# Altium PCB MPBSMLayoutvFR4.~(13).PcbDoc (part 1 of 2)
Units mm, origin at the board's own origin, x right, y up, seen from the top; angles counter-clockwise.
Board outline 131.7 x 110.39 mm, 4 copper layers (Top Layer, Power, GroundPlane, Bottom Layer), stack 2.286 mm thick; 156 components, 77 nets, 429 pads, 117 vias.
Unrouted connection lines stored in the file: 25.
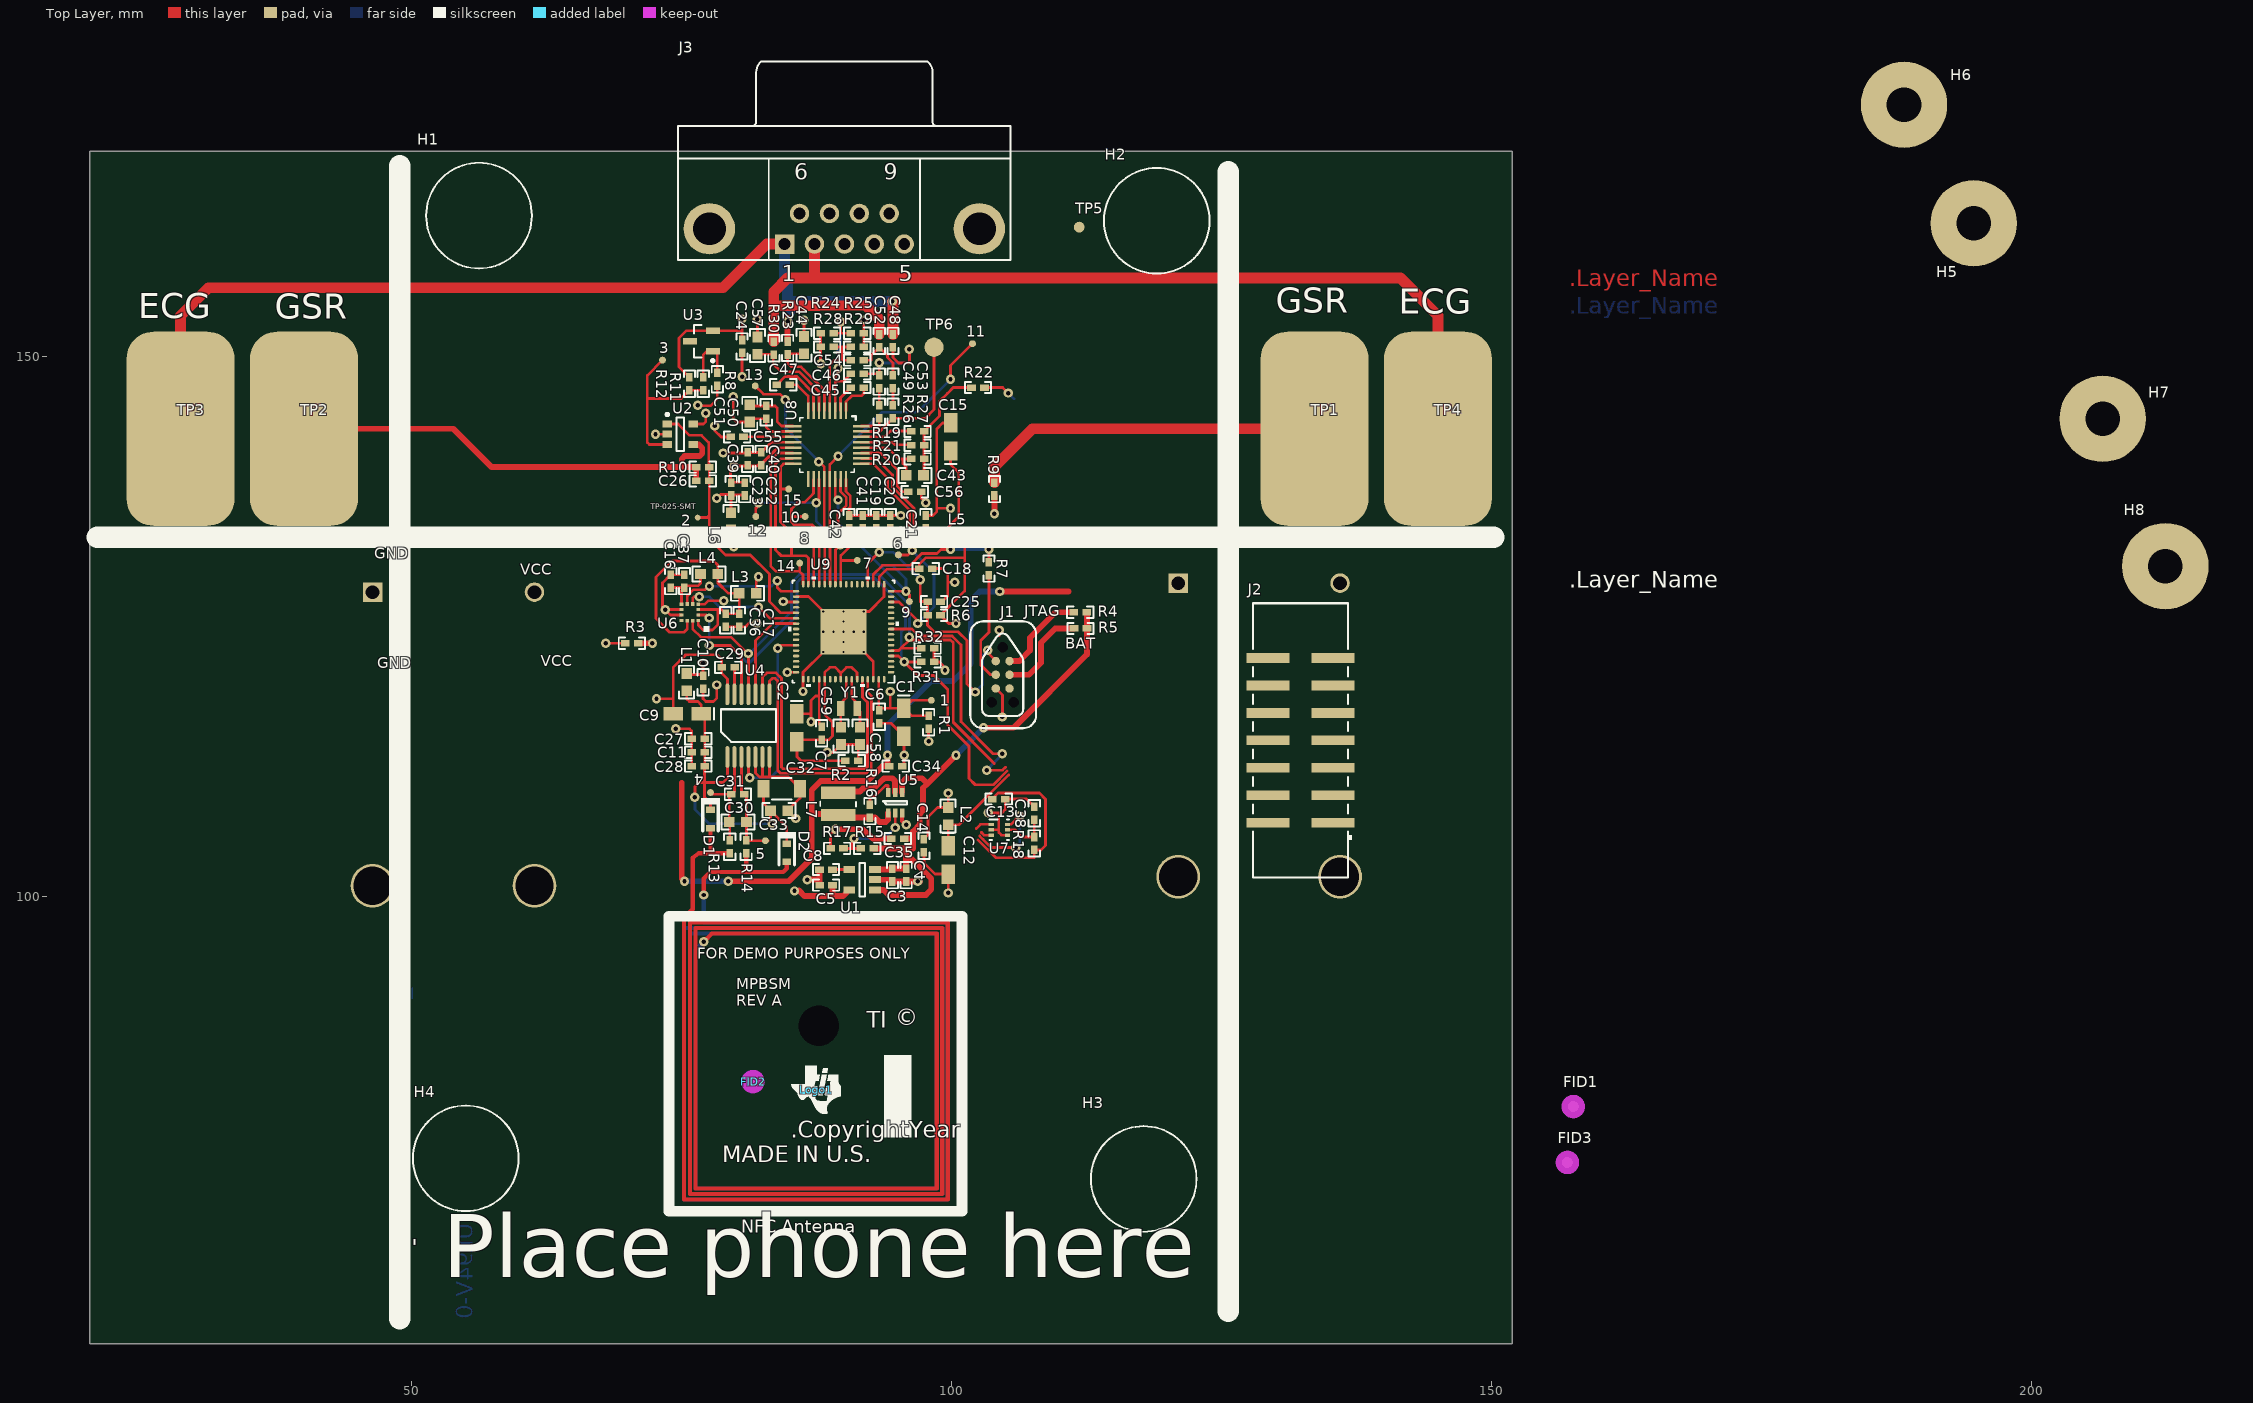
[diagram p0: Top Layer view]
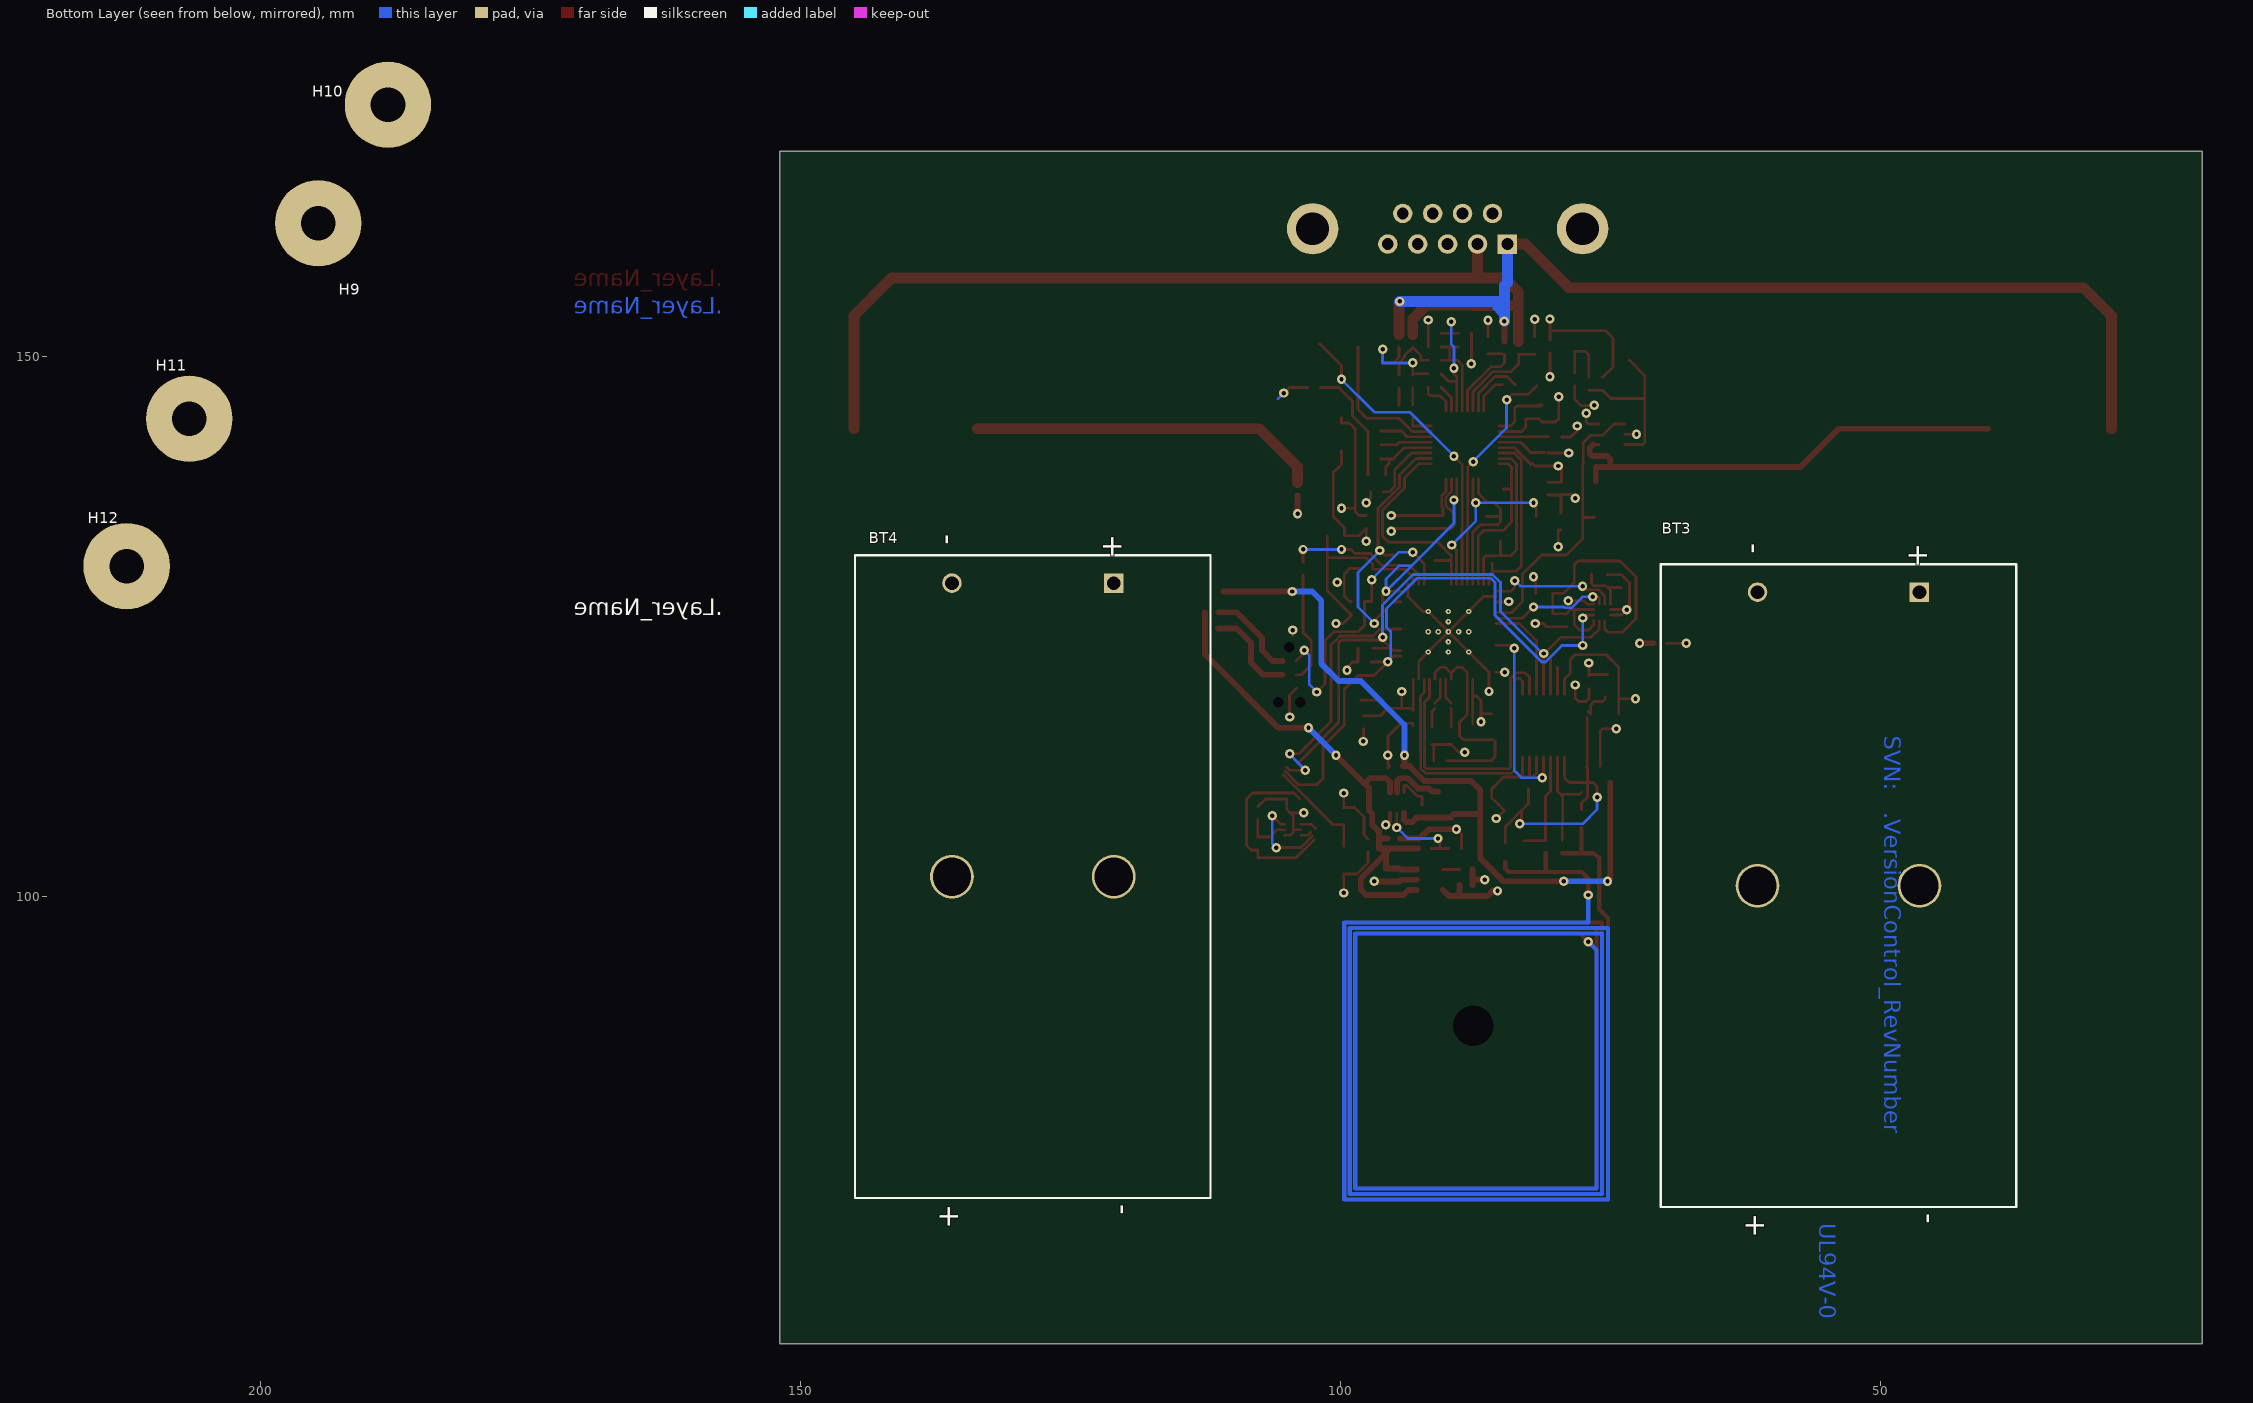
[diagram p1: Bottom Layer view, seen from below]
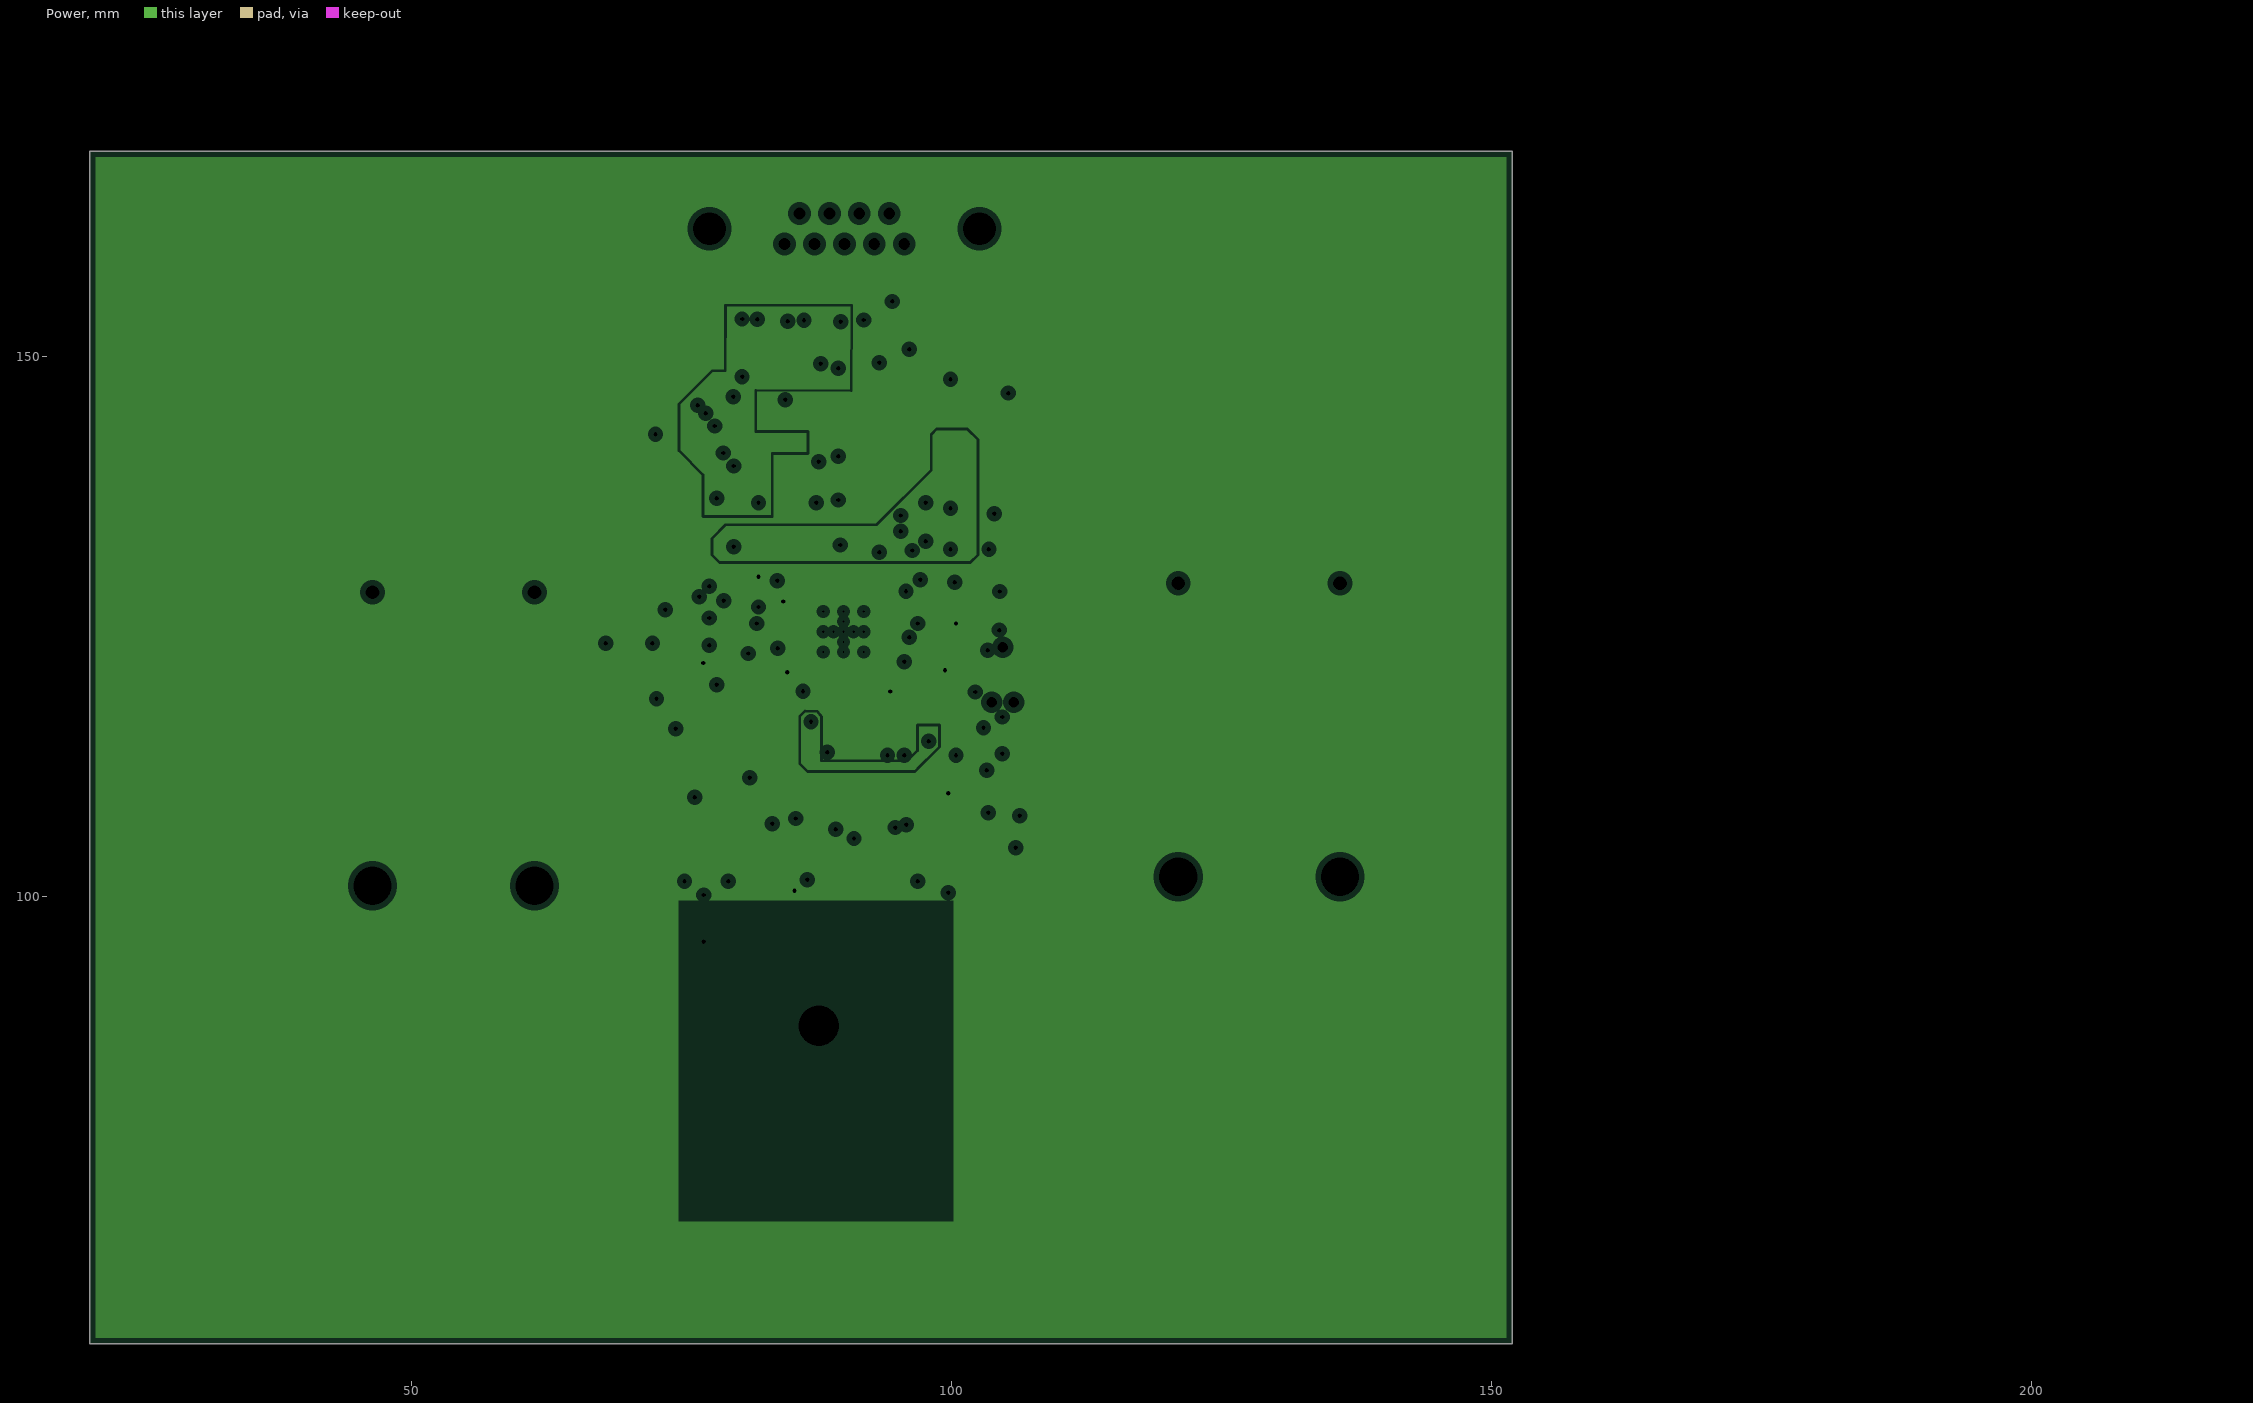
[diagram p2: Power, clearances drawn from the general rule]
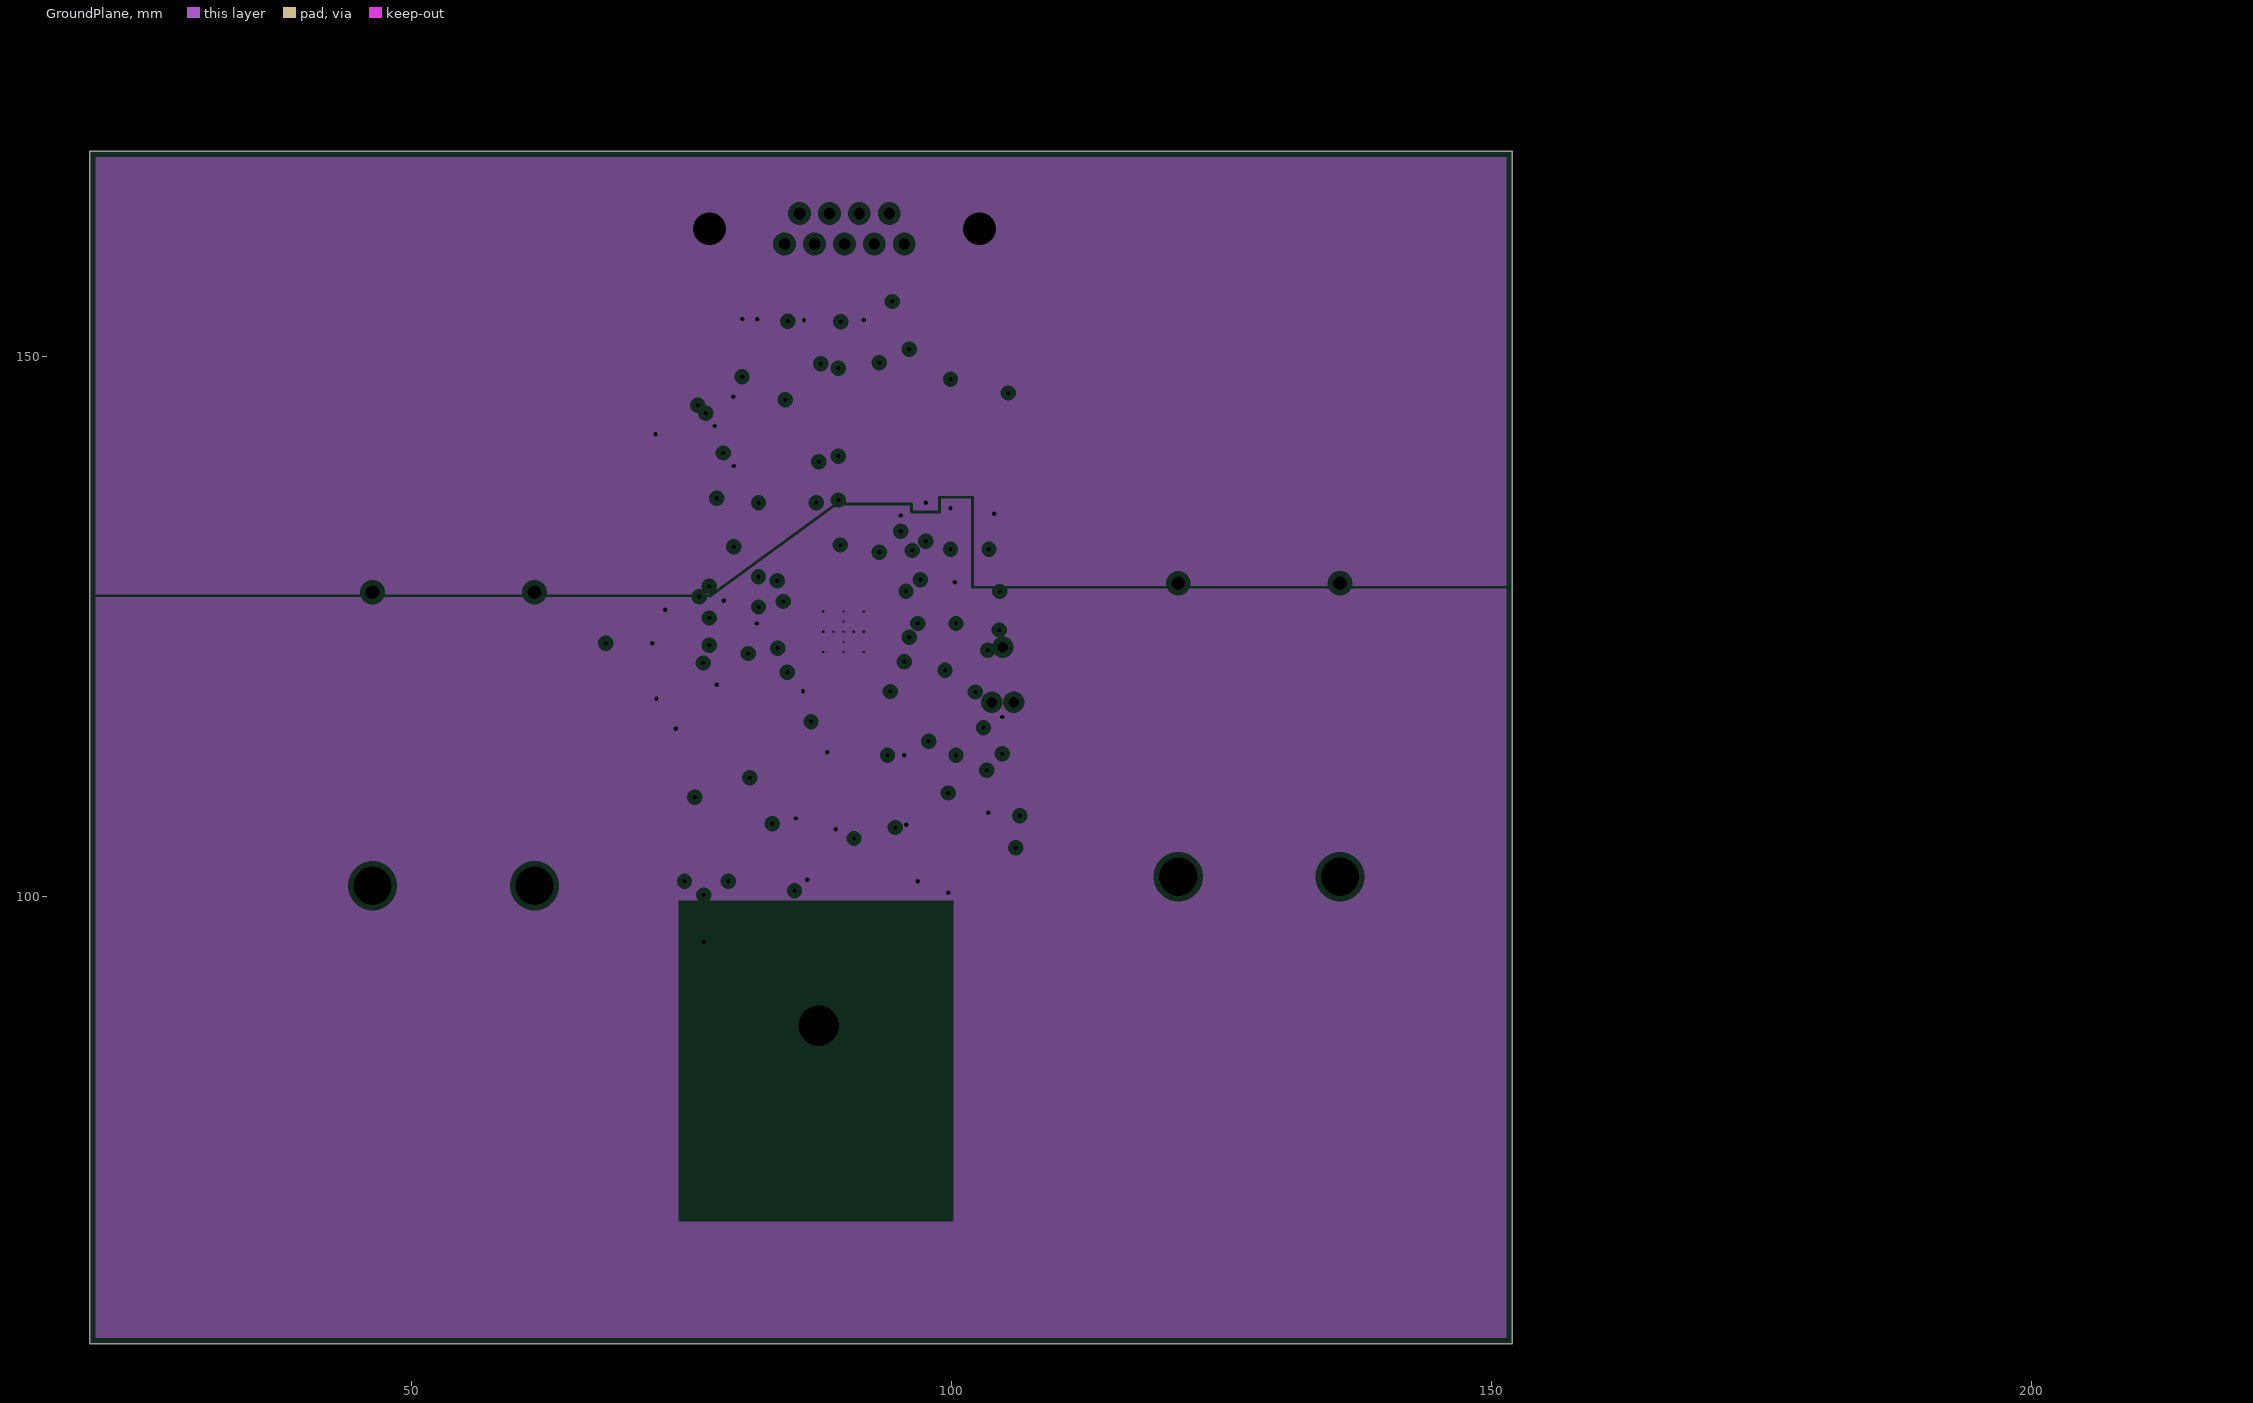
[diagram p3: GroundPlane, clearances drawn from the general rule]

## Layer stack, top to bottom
Top Solder: solder mask 0.0102, Solder Resist, Dk 3.5
Top Layer: signal copper 0.0356
Dielectric1: core 1.5037, FR-4, Dk 4.8
Power: plane copper 0.0356, net DVCC
Dielectric2: prepreg 0.32, FR-4, Dk 4.8
GroundPlane: plane copper 0.0356, net GND
Dielectric3: core 0.32, FR-4, Dk 4.8
Bottom Layer: signal copper 0.0356
Bottom Solder: solder mask 0.0102, Solder Resist, Dk 3.5

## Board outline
20.218,169.037 20.218,58.649 150.825,58.649 151.917,58.649 151.917,158.471 151.917,169.037 20.218,169.037

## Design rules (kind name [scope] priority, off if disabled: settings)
AcuteAngle [All] p1: minimum=4.50000000000000E+0001 checktracksonly=FALSE
AssemblyTestPointUsage [All] p1: valid=2
Clearance Clearance_BoardEdge_MountingHoles [OnCopper and InComponentClass('Mounting Holes') vs IsKeepOut] p1: gap=1.016
Clearance Clearance_BoardEdge_Poly [OnCopper and InPoly vs IsKeepOut] p2: gap=0.635
Clearance Clearance_BoardEdge [OnCopper and Not InComponentClass('Logo') and not InComponentClass('FiducialMark') and not InRegion(1000,500,4000,800) and Not IsKeepout vs IsKeepOut] p3: gap=1.905
Clearance Clearance_Poly [InPolygon] p4: gap=0.635
Clearance [All] p5: gap=0.1
ComponentClearance ComponentClearance_Shunt [InComponentClass('Header') vs InComponentClass('Shunt')] p1: gap=0 collisioncheckmode=3 verticalgap=0 showdistances=FALSE
ComponentClearance ComponentClearance_MountingHoles_FiducialMarks [InComponentClass('Mounting Holes') vs InComponentClass('FiducialMark')] p2: gap=1.27 collisioncheckmode=3 verticalgap=0.254 showdistances=FALSE
ComponentClearance ComponentClearance_Logo [InComponentClass('Logo')] p3: gap=1.27 collisioncheckmode=3 verticalgap=0.254 showdistances=FALSE
ComponentClearance ComponentClearance_ScrewToNut [(HasFootprint('NY PMS 440 0025 PH')) vs (HasFootprint('Keystone_1902C'))] p4: gap=0.127 collisioncheckmode=3 verticalgap=0.254 showdistances=FALSE
ComponentClearance ComponentClearance_MountingHoles [InComponentClass('Mounting Holes')] p5: gap=6.35 collisioncheckmode=3 verticalgap=2540 showdistances=FALSE
ComponentClearance ComponentClearance_SmallPassives [HasFootprint('0201*') or HasFootprint('0402*') or HasFootprint('0508') or HasFootprint('0603*') or HasFootprint('0612') or HasFootprint('0805*') or HasFootprint('0815*') or HasFootprint('0830*') or HasFootprint('1206*') or HasFootprint('1210*') or HasFootprint('1808*') or HasFootprint('1812*') or HasFootprint('1825*') or HasFootprint('2010*') or HasFootprint('2220*') or HasFootprint('2225*') or HasFootprint('2512*') or HasFootprint('2728*') or HasFootprint('3518*') vs HasFootprint('0201*') or HasFootprint('0402*') or HasFootprint('0508') or HasFootprint('0603*') or HasFootprint('0612') or HasFootprint('0805*') or HasFootprint('0815*') or HasFootprint('0830*') or HasFootprint('1206*') or HasFootprint('1210*') or HasFootprint('1808*') or HasFootprint('1812*') or HasFootprint('1825*') or HasFootprint('2010*') or HasFootprint('2220*') or HasFootprint('2225*') or HasFootprint('2512*') or HasFootprint('2728*') or HasFootprint('3518*')] p6: gap=0.508 collisioncheckmode=3 verticalgap=0.254 showdistances=FALSE
ComponentClearance ComponentClearance_THtoSMT [IsThruComponent vs IsSMTComponent] p7: gap=2.54 collisioncheckmode=3 verticalgap=0.762 showdistances=FALSE
ComponentClearance ComponentClearance_THtoTH [IsThruComponent vs IsThruComponent] p8: gap=3 collisioncheckmode=3 verticalgap=0.762 showdistances=FALSE
ComponentClearance [All] p9: gap=1.016 collisioncheckmode=3 verticalgap=0.254 showdistances=FALSE
DiffPairsRouting [All] p1: maxlimit=2.54 minlimit=0.254 mostfreqgap=0.254 toplayer_minwidth=0.381 toplayer_maxwidth=0.381 toplayer_prefwidth=0.381 bottomlayer_minwidth=0.381 bottomlayer_maxwidth=0.381 bottomlayer_prefwidth=0.381 maxuncoupledlength=25.4
FabricationTestPointUsage TestPointUsage [All] p1: valid=2 allowmultiple=FALSE
FabricationTestpoint Testpoint [All] p1: side=3 testpointundercomponent=TRUE minsize=1.016 maxsize=2.54 preferedsize=1.524 minholesize=0 maxholesize=1.016 preferedholesize=0.813 testpointgrid=0.025 allowsidetop=TRUE allowsidebottom=TRUE usegrid=TRUE gridtolerance=0
FanoutControl Fanout_LCC [IsLCC] p1: bgadir=Out bgaviamode=Centered fanoutstyle=Auto fanoutdirection=Alternating viagrid=0.025 // Fanout_LCC (Default Rule)
FanoutControl Fanout_BGA [IsBGA] p2: bgadir=Out bgaviamode=Centered fanoutstyle=Auto fanoutdirection=Alternating viagrid=0.025 // Fanout_BGA (Default Rule)
FanoutControl Fanout_Default [All] p4: bgadir=Out bgaviamode=Centered fanoutstyle=Auto fanoutdirection=Alternating viagrid=0.025 // Fanout_Default (Default Rule)
FanoutControl Fanout_Small [(CompPinCount < 5)] p5: bgadir=Out bgaviamode=Centered fanoutstyle=Auto fanoutdirection=OutThenIn viagrid=0.025 // Fanout_Small (Default Rule)
Height [All] p1: minheight=0 maxheight=55.4 prefheight=12.7
HoleSize [All] p1: absolutevalues=TRUE maxlimit=6.375 minlimit=0.1 maxpercent=80.000 minpercent=20.000
MinimumAnnularRing MinimumAnnularRing_ThermalPadVias [IsVia and InAnyComponent] p1: minimumring=0.15
MinimumAnnularRing [All] p2: minimumring=0.229
MinimumSolderMaskSliver MinimumSolderMaskSliver_Logo [InComponentClass('Logo') vs InComponentClass('Logo')] p1: minsoldermaskwidth=0.018
MinimumSolderMaskSliver [All] p2: minsoldermaskwidth=0.08
PlaneClearance [All] p1: clearance=0.508
PlaneConnect [All] p1: planeconnectstyle=Relief reliefexpansion=0.254 reliefentries=4 reliefconductorwidth=0.254 reliefairgap=0.254
PolygonConnect [All] p1: connectstyle=Relief reliefconductorwidth=0.254 reliefentries=4 polygonreliefangle="90 Angle" airgapwidth=0.254
RoutingVias ThermalPadVias [IsVia and InAnyComponent] p1: holewidth=0.2 width=0.5 viastyle="Through Hole" minholewidth=0.2 minwidth=0.5 maxholewidth=0.33 maxwidth=0.6
RoutingVias [All] p2: holewidth=0.406 width=0.864 viastyle="Through Hole" minholewidth=0.2 minwidth=0.66 maxholewidth=1.016 maxwidth=1.651
SMDToCorner [All] p1: distance=30000
SilkToSilkClearance SilkToSilkClearance_Pb-FreeLogo [(HasFootprint('Pb-Free_Overlay_Medium') OR HasFootprint('Pb-Free_Overlay_Small')) vs (HasFootprint('Pb-Free_Overlay_Medium') OR HasFootprint('Pb-Free_Overlay_Small'))] p1: silktosilkclearance=0
SilkToSilkClearance [All] p2: silktosilkclearance=0
SilkToSolderMaskClearance SilkscreenOverComponentPads [IsPad] p1: minsilkscreentomaskgap=0.127 clearancetoexposedcopper=TRUE
SolderMaskExpansion [All] p1: expansion=0.05
Width [All] p1: maxlimit=2.54 minlimit=0.152 preferedwidth=0.254 checkconnectedcopper=TRUE
14 further rules are at their usual default settings.

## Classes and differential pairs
component class Logo: Logo1
component class Designator: FID1 FID2 FID3 H1 H2 H3 H4 H5 H6 H7 H8 H9 H10 H11 H12 Logo1 ZZ1 ZZ2 ZZ3 ZZ4
component class FiducialMark: FID1 FID2 FID3
component class AssemblyNote: ZZ1 ZZ2 ZZ3 ZZ4
component class Battery: BT3 BT4 U?
component class BMA280: C36 C37 U6
component class "Boost Converter": C34 C35 L7 R15 R16 R17 U5
component class ECG: 6 7 8 9 10 11 12 13 14 15 C39 C40 C41 C42 C43 C44 C45 C46 C47 C48 C49 C50 C51 C52 C53 C54 C55 C56 C57 R19 R20 R21 R22 R23 R24 R25 R26 R27 R28 R29 R30 TP6 U8
component class GSR: 2 3 C26 R8 R9 R10 R11 R12 U2 U3
component class "JTAG SPY-BY-WIRE": C25 J1 J2 R4 R5 R6 R7
component class MSP430FR5XXX: C58 C59 R31 R32 U9 Y1
component class "Power Filtering": 1 C1 C2 C3 C4 C5 C6 C7 C8 C9 C10 C11 C12 C13 C14 C15 C16 C17 C18 C19 C20 C21 C22 C23 C24 L1 L2 L3 L4 L5 L6 R1 R2 R3 U1
component class Temperature: C38 R18 U7
component class Transponder: 4 5 C27 C28 C29 C30 C31 C32 C33 D1 D2 R13 R14 U4
component class "Analog Connector": J3
component class "Mounting Holes": H5 H6 H7 H8

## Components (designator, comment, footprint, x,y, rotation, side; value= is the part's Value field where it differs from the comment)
1 "TP-025-SMT" TP_25MIL-SMT#1 98.146,118.212 r90 top
2 "TP-025-SMT" TP_25MIL-SMT#2 76.505,135.128 r0 top
3 "TP-025-SMT" TP_25MIL-SMT#1 73.254,149.708 r0 top
4 "TP-025-SMT" TP_25MIL-SMT#1 77.694,109.676 r0 top
5 "TP-025-SMT" TP_25MIL-SMT#1 82.779,105.207 r270 top
6 "TP-025-SMT" TP_25MIL-SMT#1 95.098,131.674 r0 top
7 "TP-025-SMT" TP_25MIL-SMT#1 91.288,131.166 r0 top
8 "TP-025-SMT" TP_25MIL-SMT#1 85.192,133.198 r0 top
9 "TP-025-SMT" TP_25MIL-SMT#1 96.114,127.356 r0 top
10 "TP-025-SMT" TP_25MIL-SMT#1 86.462,135.23 r0 top
11 "TP-025-SMT" TP_25MIL-SMT#1 101.956,151.232 r0 top
12 "TP-025-SMT" TP_25MIL-SMT#1 81.89,135.23 r0 top
13 "TP-025-SMT" TP_25MIL-SMT#1 81.839,147.32 r0 top
14 "TP-025-SMT" TP_25MIL-SMT#1 85.954,130.912 r90 top
15 "TP-025-SMT" TP_25MIL-SMT#1 84.938,137.77 r0 top
BT3 "2462" Keystone_2462 53.899,114.63 r270 bottom
BT4 "2462" Keystone_2462 128.499,115.468 r270 bottom
C1 "293D106X9010A2TE3" 3216-18 95.606,116.18 r270 top
C2 "293D106X9010A2TE3" 3216-18 85.7,115.672 r270 top
C3 "C1005X5R1A104K" 0402 94.544,102.028 r270 top
C4 "C1005X5R0J105M" 0402 95.814,102.028 r270 top
C5 "C1005X5R1C225K050BC" 0402 88.397,101.092 r180 top
C6 "C1005X5R1A104K" 0402 93.32,116.688 r270 top
C7 "C1005X5R1A104K" 0402 87.986,115.164 r270 top
C8 "C1005X7R1E103K" 0402 88.392,102.54 r180 top
C9 "293D105X9016A2TE3" 3216-18 75.54,116.942 r180 top
C10 "C1005X5R1A104K" 0402 77.013,119.888 r270 top
C11 "C1005X5R1A104K" 0402 76.556,113.386 r180 top
C12 "293D106X9010A2TE3" 3216-18 99.703,103.422 r270 top
C13 "C1005X5R1A104K" 0402 104.379,109.068 r0 top
C14 "C1005X5R1A104K" 0402 97.462,104.75 r270 top
C15 "293D105X9016A2TE3" 3216-18 99.924,142.596 r90 top
C16 "CL05A106MQ5NUNC" 0402 74.016,129.247 r90 top
C17 "CL05A106MQ5NUNC" 0402 80.366,125.624 r270 top
C18 "C1005X5R1A104K" 0402 97.638,130.404 r0 top
C19 "C1005X5R1A104K" 0402 93.066,134.722 r90 top
C20 "C1005X5R1C225K050BC" 0402 94.336,134.722 r90 top
C21 "CL05A106MQ5NUNC" 0402 97.638,134.722 r90 top
C22 "CL05A106MQ5NUNC" 0402 80.874,137.77 r90 top
C23 "C1005X5R1A104K" 0402 79.604,137.77 r90 top
C24 "C1005X5R1A104K" 0402 80.62,150.978 r90 top
C25 "C1005X8R1H222K" 0402 98.4,127.356 r0 top
C26 "C1005X7R1E103K" 0402 76.972,138.532 r180 top
C27 "C1005X5R0J105M" 0402 76.556,114.656 r180 top
C28 "C1005X5R1A104K" 0402 76.556,112.116 r180 top
C29 "GRM155R60J474KE19D" 0402 79.35,121.26 r0 top
C30 "C1608C0G1H330J" 0603 80.234,106.941 r0 top
C31 "GRM1555C1H390JA01D" 0402 80.234,109.515 r0 top
C32 "C3216X5R1A107M160AC" 1206_190 84.298,110.023 r0 top
C33 "Used in BOM report" 0603 84.044,107.991 r0 top
C34 "CL05A106MQ5NUNC" 0402 94.844,112.116 r0 top
C35 "CL05A106MQ5NUNC" 0402 95.047,105.41 r180 top
C36 "C1005X5R1A104K" 0402 79.096,125.624 r270 top
C37 "C1005X5R1A104K" 0402 75.286,129.247 r90 top
C38 "C1005X7R1E103K" 0402 107.681,107.752 r90 top
C39 "C1005X5R1C105K050BC" 0402 81.128,140.564 r270 top
C40 "C1005X5R1A104K" 0402 82.398,140.564 r270 top
C41 "C1005X5R1C105K050BC" 0402 91.796,134.722 r90 top
C42 "C1005X5R1A104K" 0402 90.526,134.722 r90 top
C43 "C0603C152K5RACTU" 0603 96.622,139.04 r180 top
C44 "GRM1885C1H302JA01D" 0603 86.36,151.091 r90 top
C45 "GRM155R61A472KA01D" 0402 91.288,147.168 r0 top
C46 "C1005X8R1H222K" 0402 91.288,148.438 r0 top
C47 "GRM155R61A472KA01D" 0402 84.43,147.422 r180 top
C48 "C1005X5R1A104K" 0402 94.59,151.486 r270 top
C49 "C1005X8R1H222K" 0402 93.32,147.722 r90 top
C50 "C1005X5R1A104K" 0402 82.855,144.872 r270 top
C51 "C1608X5R0J106M" 0603 81.331,144.78 r270 top
C52 "C1005X5R1A104K" 0402 93.32,151.486 r270 top
C53 "C1005X8R1H222K" 0402 94.59,147.722 r90 top
C54 "C1005X8R1H222K" 0402 91.288,149.708 r0 top
C55 "C1005X5R1C105K050BC" 0402 80.158,142.596 r180 top
C56 "C1005X5R1C105K050BC" 0402 96.622,137.516 r0 top
C57 "GRM1885C1H302JA01D" 0603 82.038,151.063 r90 top
C58 "06035A100JAT2A" 0603 91.542,114.91 r270 top
C59 "06035A100JAT2A" 0603 89.789,114.91 r270 top
D1 "CDBU0130L" SOD-523F 77.694,107.229 r270 top
D2 "CDBU0130L" SOD-523F 84.76,104.089 r270 top
FID1 "Fiducial" Fiducial10-20 157.582,80.594 r0 top
FID2 "Fiducial" Fiducial10-20 81.636,82.906 r0 top
FID3 "Fiducial" Fiducial10-20 157.048,75.413 r0 top
H1 "SJ61A2" Bumpon_SJ61A2 56.261,163.093 r0 top
H2 "SJ61A2" Bumpon_SJ61A2 119.024,162.611 r0 top
H3 "SJ61A2" Bumpon_SJ61A2 117.805,73.889 r0 top
H4 "SJ61A2" Bumpon_SJ61A2 55.042,75.794 r0 top
H5 "NY PMS 440 0025 PH" "NY PMS 440 0025 PH" 194.666,162.382 r90 top
H6 "NY PMS 440 0025 PH" "NY PMS 440 0025 PH" 188.214,173.355 r90 top
H7 "NY PMS 440 0025 PH" "NY PMS 440 0025 PH" 206.604,144.272 r90 top
H8 "NY PMS 440 0025 PH" "NY PMS 440 0025 PH" 212.421,130.638 r90 top
H9 "1902C" Keystone_1902C 194.665,162.376 r90 bottom
H10 "1902C" Keystone_1902C 188.239,173.33 r90 bottom
H11 "1902C" Keystone_1902C 206.604,144.272 r90 bottom
H12 "1902C" Keystone_1902C 212.42,130.632 r180 bottom
J1 "TC2030-MCP-NL" TC2030-MCP-NL 104.75,120.574 r180 top
J2 "61201420621" Wurth_61201420621 132.334,114.503 r180 top
J3 "182-009-213R171" NORCOMP_182-009-213R171 90.094,171.374 r0 top
L1 "BLM18HG601SN1D" 0603 75.489,119.888 r270 top
L2 "BLM18HG601SN1D" 0603 99.703,107.486 r270 top
L3 "BLM18HG601SN1D" 0603 81.128,128.118 r180 top
L4 "BLM18HG601SN1D" 0603 77.572,129.896 r0 top
L5 "BLM18HG601SN1D" 0603 100.432,133.452 r180 top
L6 "BLM18HG601SN1D" 0603 79.604,134.772 r90 top
L7 "EPL3015-472MLB" EPL3015 89.535,108.61 r90 top
Logo1 "Texas Instruments" TI_Symbol_Overlay_Small 87.478,82.144 r0 top
R1 "ERJ-2GE0R00X" 0402 97.892,116.18 r270 top
R2 "ERJ-2GE0R00X" 0402 90.78,112.624 r180 top
R3 "ERJ-2GE0R00X" 0402 70.418,123.489 r180 top
R4 "ERJ-2GE0R00X" 0402 111.938,126.365 r0 top
R5 "ERJ-2GE0R00X" 0402 111.957,124.861 r0 top
R6 "CRCW040247K0JNED" 0402 98.4,126.086 r0 top
R7 "ERJ-2GE0R00X" 0402 103.48,130.404 r90 top
R8 "CRCW040221K5FKED" 0402 78.334,147.93 r270 top
R9 "CRCW040210K0FKED" 0402 103.988,137.77 r90 top
R10 "ERJ-2RKF1004X" 0402 76.972,139.802 r0 top
R11 "CRCW040211K8FKED" 0402 77.018,147.517 r90 top
R12 "CRCW04028K06FKED" 0402 75.748,147.517 r270 top
R13 "ERJ-2GE0R00X" 0402 79.472,104.655 r270 top
R14 "ERJ-2GE0R00X" 0402 80.996,104.655 r270 top
R15 "ERJ-2RKF1004X" 0402 92.212,104.496 r0 top
R16 "ERJ-2GE0R00X" 0402 92.456,107.95 r90 top
R17 "ERJ-2RKF2003X" 0402 89.418,104.496 r0 top
R18 "CRCW04024K99FKED" 0402 107.681,104.958 r270 top
R19 "ERJ-2GE0R00X" 0402 96.876,143.104 r0 top
R20 "ERJ-2RKF1004X" 0402 96.876,140.564 r0 top
R21 "ERJ-2RKF1003X" 0402 96.876,141.834 r0 top
R22 "ERJ-2RKF1003X" 0402 102.464,147.168 r0 top
R23 "CRCW040251K1FKED" 0402 84.836,150.837 r270 top
R24 "CRCW040210M0FKED" 0402 88.494,152.202 r180 top
R25 "CRCW040210M0FKED" 0402 91.288,152.202 r180 top
R26 "CRCW040240K2FKED" 0402 93.32,144.928 r270 top
R27 "CRCW040240K2FKED" 0402 94.59,144.928 r270 top
R28 "CRCW040210M0FKED" 0402 88.494,150.932 r180 top
R29 "CRCW040210M0FKED" 0402 91.288,150.932 r180 top
R30 "CRCW040251K1FKED" 0402 83.562,150.809 r270 top
R31 "CRCW04023K30JNED" 0402 97.8,121.768 r180 top
R32 "CRCW04023K30JNED" 0402 97.8,123.038 r180 top
TP1 "TESTPOINT" TP_SM_1MM#1 133.629,143.358 r0 top
TP2 "TESTPOINT" TP_SM_1MM#2 40.056,143.358 r90 top
TP3 "TESTPOINT" TP_SM_1MM#2 28.626,143.358 r90 top
TP4 "TESTPOINT" TP_SM_1MM#2 145.059,143.358 r90 top
TP5 "TESTPOINT" TP_SM_1MM#3 111.836,162.027 r90 top
TP6 "Pogo Pad" PogoPad 98.4,150.901 r0 top locked
U1 "TPS73030DBVR" DBV0005A_N 91.745,101.6 r180 top
U2 "LMP2231AMFE" MF05A_L 74.894,142.85 r0 top
U3 "LM4041AIM3-1.2" MF03A_N 76.86,151.46 r180 top
U4 "RF430CL331HCPW" PW0014A_M 81.21,115.864 r90 top
U5 "TPS61220DCK" DCK0006A_N 94.793,108.712 r90 top
U6 "BMA280" LGA-12P 75.794,126.361 r90 top
U7 "TMP112AIDRL" DRL0006A 104.453,106.221 r0 top
U8 "ADS1292RIPBS" PBS0032A_N 88.494,141.853 r270 top
U9 "MSP430FR5889IRGCR" RGC0064B 90.018,124.562 r180 top
Y1 "FC-12M 32.7680KA-A3" Epson_FC-12M 90.526,117.45 r0 top
ZZ1 "This Assembly Note is for PCB labels only" AssemblyNoteLabel 35.992,195.631 r0 top
ZZ2 "These assemblies are ESD sensitive, ESD precautions shall be observed." AssemblyNote 35.992,192.865 r0 top
ZZ3 "These assemblies must be clean and free from flux and all contaminants. Use of no clean flux is not acceptable." AssemblyNote 35.992,190.616 r0 top
ZZ4 "These assemblies must comply with workmanship standards IPC-A-610 Class 2, unless otherwise specified." AssemblyNote 35.992,188.366 r0 top

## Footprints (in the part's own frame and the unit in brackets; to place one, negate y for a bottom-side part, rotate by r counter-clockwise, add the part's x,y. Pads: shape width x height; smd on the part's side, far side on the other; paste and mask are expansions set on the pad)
0402 [mm] "0402 from SM-752 data"
  rect 0.8x0.6 smd: 1(-0.6,0) 2(0.6,0)
  silkscreen extent -1.22,-0.52 1.22,0.52, body extent -0.55,-0.3 0.55,0.3, height 0.6
0603 [mm] "0603 from SM-752 data"
  rect 1x0.95 smd: 1(-0.8,0) 2(0.8,0)
  silkscreen extent -1.52,-0.69 1.52,0.69, body extent -0.87,-0.47 0.87,0.47, height 0.85
1206_190 [mm] "1206_190"
  rect 1.1x1.6 smd: 1(-1.7,0) 2(1.7,0)
  silkscreen extent -0.9,-1 0.9,1, body extent -1.75,-0.95 1.75,0.95, height 1.9
3216-18 [mm] "Medium density IPC, based on Kemet T495 dimensions"
  rect 1.8x1.25 smd: 1(-1.3,0) 2(1.3,0)
  silkscreen extent -2.49,-0.54 -2.49,0.54, body extent -1.7,-0.9 1.7,0.9, height 1.8
AssemblyNote [mm] "Assembly Note"
AssemblyNoteLabel [mm] "Assembly Note for PCB Labels"
Bumpon_SJ61A2 [mil] "3M Hemispherical Bumpon transparent"
  round 1 on Mech3: 0(0,0)
  silkscreen extent -192,-192 192,192, body extent -191,-192 193,192, height 250
DBV0005A_N [mm] "SOT23, 5-Leads, Body 2.9x1.6mm, Pitch 0.95mm, Lead Span 2.8mm, IPC Medium Density"
  rect 1.1x0.65 smd: 1(-1.2,0.95) 2(-1.2,0) 3(-1.2,-0.95) 4(1.2,-0.95) 5(1.2,0.95)
  silkscreen extent -0.25,-1.55 0.25,1.55, body extent -1.42,-1.46 1.42,1.46, height 1.08
DCK0006A_N [mm] "SOT23, 6-Leads, Body 2x1.3mm, Pitch 0.65mm, Lead Span 2.1mm, IPC Medium Density"
  rect 0.85x0.4 smd: 1(-0.95,0.65) 2(-0.95,0) 3(-0.95,-0.65) 4(0.95,-0.65) 5(0.95,0) 6(0.95,0.65)
  silkscreen extent -0.15,-1.1 0.15,1.1, body extent -1.14,-1 1.14,1, height 0.94
DRL0006A [mm] "SOTFL, 6-Flat Leads, Body 1.2x1.6x0.6mm, Pitch 0.5mm, TI recommended"
  rect 0.5x0.3 smd: 1(-0.75,0.5) 2(-0.75,0) 3(-0.75,-0.5) 4(0.75,-0.5) 5(0.75,0) 6(0.75,0.5)
  silkscreen extent -0.9,-0.95 0.9,0.95, body extent -0.85,-0.85 0.85,0.85, height 0.62
EPL3015 [mm] "COILCRAFT"
  rect 1.12x3.2 smd: 1(-1.04,0) 2(1.04,0)
  silkscreen extent -0.22,-1.65 0.23,1.68, body extent -1.6,-1.6 1.6,1.6, height 1.55
Epson_FC-12M [mm] "Epson"
  rect 0.7x1.4 smd: 1(-0.75,0) 2(0.75,0)
  body extent -1.05,-0.63 1.05,0.63, height 0.6
Fiducial10-20 [mm]
  round 1 smd mask+0.5: 1(0,0)
  Top Layer keep-out circle w1.178: c0,0 r0.5
Keystone_1902C [mil] "Hex Standoff, 4-40 threaded, nylon"
  round 1 on Mech4: 0(0,0)
  body extent -145,-126 146,126, height 501
Keystone_2462 [mm] "2x AA Battery Holder, Through-hole mount"
  rect 1.8x1.8 hole 1.27: 1(-13.59,7.495)
  round 1.8 hole 1.27: 2(-13.59,-7.495)
  round 4.05 hole 3.55: 3(13.59,-7.495) 4(13.59,7.495)
  silkscreen extent -16.18,-16.46 43.33,16.46, body extent -16.31,-16.46 43.4,16.46, height 16
LGA-12P [mm]
  rect 0.3x0.35 smd mask+0.05: 1(-0.75,-0.775) 2(-0.25,-0.775) 3(0.25,-0.775) 4(0.75,-0.775) 7(0.75,0.775) 8(0.25,0.775) 9(-0.25,0.775) 10(-0.75,0.775)
  rect 0.35x0.3 smd mask+0.05: 5(0.775,-0.25) 6(0.775,0.25) 11(-0.775,0.25) 12(-0.775,-0.25)
  silkscreen extent -1.8,-1.8 -1.29,-1.3
MF03A_N [mm] "SOT23, 3-Leads, Body 2.9x1.3mm, Pitch 0.95mm, Lead Span 2.4mm, IPC Medium Density"
  rect 1.3x0.6 smd: 1(-1.05,0.95) 2(-1.05,-0.95) 3(1.05,0)
  silkscreen extent -1.18,-1.5 0.7,1.92, body extent -0.7,-1.5 0.7,1.5, height 1.12
MF05A_L [mm] "SOT23, 5-Leads, Body 2.9x1.6mm, Pitch 0.95mm, Lead Span 2.8mm, IPC High Density"
  rect 0.9x0.65 smd: 1(-1.2,0.95) 2(-1.2,0) 3(-1.2,-0.95) 4(1.2,-0.95) 5(1.2,0.95)
  silkscreen extent -1.32,-1.55 0.35,1.95, body extent -0.9,-1.55 0.9,1.55, height 1.19
NORCOMP_182-009-213R171 [mm] "Connector; D Subminiature 9 Position; Right Angle"
  rect 1.8x1.8 hole 1.092: 1(-5.54,-10.92)
  round 1.8 hole 1.092: 2(-2.77,-10.92) 3(0,-10.92) 4(2.77,-10.92) 5(5.54,-10.92) 6(-4.155,-8.08) 7(-1.385,-8.08) 8(1.385,-8.08) 9(4.155,-8.08)
  round 4.76 hole 3.05: 10(-12.495,-9.5) 11(12.495,-9.5)
  silkscreen extent -15.4,-12.4 15.4,6, body extent -15.41,-12.98 15.41,6.1, height 12.55
"NY PMS 440 0025 PH" [mm] "4-40 nylon screw and mounting hole"
  round 8 hole 3.2: 1(0,0)
  body extent -3.3,-3.3 3.3,3.3, height 2.69
PBS0032A_N [mil]
  rect 60x9 smd: 1(-124,68.9) 2(-124,49.21) 3(-124,29.53) 4(-124,9.84) 5(-124,-9.84) 6(-124,-29.53) 7(-124,-49.21) 8(-124,-68.9) 17(124,-68.9) 18(124,-49.21) 19(124,-29.53) 20(124,-9.84) 21(124,9.84) 22(124,29.53) 23(124,49.21) 24(124,68.9)
  rect 9x60 smd: 9(-68.9,-124) 10(-49.21,-124) 11(-29.53,-124) 12(-9.84,-124) 13(9.84,-124) 14(29.53,-124) 15(49.21,-124) 16(68.9,-124) 25(68.9,124) 26(49.21,124) 27(29.53,124) 28(9.84,124) 29(-9.84,124) 30(-29.53,124) 31(-49.21,124) 32(-68.9,124)
  silkscreen extent -104,-100 100,104, body extent -140,-140 140,140, height 48
PogoPad [mil] "No Solder Paste"
  round 70 smd paste-35: 1(0,0)
PW0014A_M [mm] "TSOP, 14-Leads, Body 5x4.4mm, Pitch 0.65mm, IPC Low Density"
  oval 2x0.35 smd: 1(-2.9,1.95) 2(-2.9,1.3) 3(-2.9,0.65) 4(-2.9,0) 5(-2.9,-0.65) 6(-2.9,-1.3) 7(-2.9,-1.95) 8(2.9,-1.95) 9(2.9,-1.3) 10(2.9,-0.65) 11(2.9,0) 12(2.9,0.65) 13(2.9,1.3) 14(2.9,1.95)
  silkscreen extent -1.5,-2.55 1.53,2.55, body extent -3.21,-2.5 3.21,2.5, height 0.98
RGC0064B [mm]
  oval 0.6x0.24 smd mask+0.07: 1(-4.4,3.75) 2(-4.4,3.25) 3(-4.4,2.75) 4(-4.4,2.25) 5(-4.4,1.75) 6(-4.4,1.25) 7(-4.4,0.75) 8(-4.4,0.25) 9(-4.4,-0.25) 10(-4.4,-0.75) 11(-4.4,-1.25) 12(-4.4,-1.75) 13(-4.4,-2.25) 14(-4.4,-2.75) 15(-4.4,-3.25) 16(-4.4,-3.75) 33(4.4,-3.75) 34(4.4,-3.25) 35(4.4,-2.75) 36(4.4,-2.25) 37(4.4,-1.75) 38(4.4,-1.25) 39(4.4,-0.75) 40(4.4,-0.25) 41(4.4,0.25) 42(4.4,0.75) 43(4.4,1.25) 44(4.4,1.75) 45(4.4,2.25) 46(4.4,2.75) 47(4.4,3.25) 48(4.4,3.75)
  oval 0.24x0.6 smd mask+0.07: 17(-3.751,-4.4) 18(-3.251,-4.4) 19(-2.751,-4.4) 20(-2.251,-4.4) 21(-1.75,-4.4) 22(-1.25,-4.4) 23(-0.75,-4.4) 24(-0.25,-4.4) 25(0.25,-4.4) 26(0.75,-4.4) 27(1.25,-4.4) 28(1.75,-4.4) 29(2.251,-4.4) 30(2.751,-4.4) 31(3.251,-4.4) 32(3.751,-4.4) 49(3.751,4.4) 50(3.251,4.4) 51(2.751,4.4) 52(2.251,4.4) 53(1.75,4.4) 54(1.25,4.4) 55(0.75,4.4) 56(0.25,4.4) 57(-0.25,4.4) 58(-0.75,4.4) 59(-1.25,4.4) 60(-1.75,4.4) 61(-2.251,4.4) 62(-2.751,4.4) 63(-3.251,4.4) 64(-3.751,4.4)
  rect 4.25x4.25 smd paste-2.112: 65(0,0)
  silkscreen extent -5.1,-5.1 5.1,5.1, body extent -4.57,-4.57 4.57,4.57, height 1.01
SOD-523F [mm] "COMCHIP"
  rect 0.6x0.8 smd paste-0.05: 1(-0.85,0) 2(0.85,0)
  silkscreen extent -1.92,-0.87 1.1,0.88, body extent -0.9,-0.5 0.9,0.5, height 0.85
TC2030-MCP-NL [mil] "TAG-CONNECT"
  round 31 smd paste-16: 1(-25,-50) 2(25,-50) 3(-25,0) 4(25,0) 5(-25,50) 6(25,50)
  round 25 hole 39 unplated: MH1(0,-100) MH2(-40,100) MH3(40,100)
  silkscreen extent -122,-195 118,195
TI_Symbol_Overlay_Small [mm]
  silkscreen extent -2.3,-2.23 2.3,2.24
TP_25MIL-SMT#1 [mm]
  round 0.635 smd mask-0.064: 1(0,0)
TP_25MIL-SMT#2 [mm]
  round 0.535 smd mask-0.064: 1(0,0)
TP_SM_1MM#1 [mm] "1mm Test Point, SMT"
  rrect50% 10x18 smd paste-0.5: 1(0,0)
TP_SM_1MM#2 [mm] "1mm Test Point, SMT"
  rrect50% 18x10 smd paste-0.5: 1(0,0)
TP_SM_1MM#3 [mm] "1mm Test Point, SMT"
  round 1 smd paste-0.5: 1(0,0)
Wurth_61201420621 [mm] "Header, 2.54mm, 7x2, SMT"
  rect 4x0.9 smd: 1(-3,7.62) 2(3,7.62) 3(-3,5.08) 4(3,5.08) 5(-3,2.54) 6(3,2.54) 7(-3,0) 8(3,0) 9(-3,-2.54) 10(3,-2.54) 11(-3,-5.08) 12(3,-5.08) 13(-3,-7.62) 14(3,-7.62)
  silkscreen extent -4.75,-12.7 4.4,12.7, body extent -4.75,-12.7 4.75,12.7, height 10.43

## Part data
1 2 3 4 5 6 7 8 9 10 11 12 13 14 15: "Test Point, O.025\""
BT3 BT4: "2x AA Battery Holder, Through-hole mount"
C1 C2 C12: "CAP, TA, 10 µF, 10 V, +/- 10%, 3.4 ohm, SMD"
C3 C6 C7 C10 C11 C13 C14 C18 C19 C23 C24 C28 C36 C37 C40 C42 C48 C50 C52: "CAP, CERM, 0.1 µF, 10 V, +/- 10%, X5R, 0402"
C4 C27: "CAP, CERM, 1 µF, 6.3 V, +/- 20%, X5R, 0402"
C5 C20: "CAP, CERM, 2.2 µF, 16 V, +/- 10%, X5R, 0402"
C8 C26 C38: "CAP, CERM, 0.01 µF, 25 V, +/- 10%, X7R, 0402"
C9 C15: "CAP, TA, 1 µF, 16 V, +/- 10%, 9.3 ohm, SMD"
C16 C17 C21 C22 C34 C35: "CAP, CERM, 10 µF, 6.3 V, +/- 20%, X5R, 0402"
C25 C46 C49 C53 C54: "CAP, CERM, 2200 pF, 50 V, +/- 10%, X8R, 0402"
C29: "CAP, CERM, 0.47 µF, 6.3 V, +/- 10%, X5R, 0402"
C30: "CAP, CERM, 33 pF, 50 V, +/- 5%, C0G/NP0, 0603"
C31: "CAP, CERM, 39pF, 50V, +/-5%, C0G/NP0, 0402"
C32: "CAP, CERM, 100 µF, 10 V, +/- 20%, X5R, 1206_190"
C33: library part Capacitor, "CAP, CERM, xxxF, xxV, [TempCo], xx%, [PackageReference]"
C39 C41 C55 C56: "CAP, CERM, 1 µF, 16 V, +/- 10%, X5R, 0402"
C43: "CAP, CERM, 1500 pF, 50 V, +/- 10%, X7R, 0603"
C44 C57: "CAP, CERM, 3000 pF, 50 V, +/- 5%, C0G/NP0, 0603"
C45 C47: "CAP, CERM, 4700 pF, 10 V, +/- 10%, X5R, 0402"
C51: "CAP, CERM, 10 µF, 6.3 V, +/- 20%, X5R, 0603"
C58 C59: "CAP, CERM, 10 pF, 50 V, +/- 5%, C0G/NP0, 0603"
D1 D2: "Diode, Schottky, 35V, 0.1A, SOD-523F"
FID1 FID2 FID3: "Fiducial mark.  There is nothing to buy or mount."
H1 H2 H3 H4: "Bumpon, Hemisphere, 0.375 X 0.235, Black"
H5 H6 H7 H8: "Machine Screw, Round, #4-40 x 1/4, Nylon, Philips panhead"
H9 H10 H11 H12: "Standoff, Hex, 0.5\"L #4-40 Nylon"
J1: "Footprint for TC2030-MCP-NL"
J2: "Header(Shrouded), 2.54mm, 7x2, Gold, Black, SMT"
J3: "CONN DB9 FEMALE R/A SOLDER TH"
L1 L2 L3 L4 L5 L6: "Ferrite Bead, 600 ohm @ 100MHz, 0.2A, 0603"
L7: "Inductor, Shielded, Ferrite, 4.7uH, 1.2A, 0.14 ohm, SMD"
Logo1: library part TI_Logo, "Texas Instrument Corporate Signature"
R1 R2 R3 R4 R5 R7 R13 R14 R16 R19: "RES, 0, 5%, 0.063 W, 0402"
R6: "RES, 47 k, 5%, 0.063 W, 0402"
R8: "RES, 21.5 k, 1%, 0.063 W, 0402"
R9: "RES, 10.0 k, 1%, 0.063 W, 0402"
R10 R15 R20: "RES, 1.00 M, 1%, 0.1 W, 0402"
R11: "RES, 11.8 k, 1%, 0.063 W, 0402"
R12: "RES, 8.06 k, 1%, 0.063 W, 0402"
R17: "RES, 200 k, 1%, 0.1 W, 0402"
R18: "RES, 4.99 k, 1%, 0.063 W, 0402"
R21 R22: "RES, 100 k, 1%, 0.1 W, 0402"
R23 R30: "RES, 51.1 k, 1%, 0.063 W, 0402"
R24 R25 R28 R29: "RES, 10.0 M, 1%, 0.063 W, 0402"
R26 R27: "RES, 40.2 k, 1%, 0.063 W, 0402"
R31 R32: "RES, 3.3 k, 5%, 0.063 W, 0402"
TP1 TP2 TP3 TP4 TP5: library part TP_SM_1MM, "1mm Test Point, SMT"
TP6: library part PogoPad, "Pad for Pogo Pin Connector"
U1: "Single Output High PSRR LDO, 200 mA, Fixed 3 V Output, 2.7 to 5.5 V Input, 5-pin SOT-23 (DBV), -40 to 85 degC, Green (RoHS & no Sb/Br)"
U2: "Single Micropower Precision Op Amp"
U3: "Precision Micropower Shunt Voltage Reference, 3-pin SOT-23"
U4: library part RF430CL331H, "The Texas Instruments Dynamic NFC Interface Transponder RF430CL331H is an NFC Tag Type 4 device  that combines a wireless NFC interface and a wired SPI or I2C interface to connect the device to a host."
U5: "LOW INPUT VOLTAGE STEP-UP CONVERTER IN 6 PIN SC-70 PACKAGE, DCK0006A"
U6: library part BMA250, "14 bit, digital, triaxial acceleration sensor with intelligent on-chip motion triggered interrupt controller"
U7: "High-Accuracy, Low-Power, Digital Temperature Sensor With SMBus(TM)/Two-Wire Serial Interface, DRL0006A"
U8: "Low-Power, 2-Channel, 24-Bit Analog Front-End for Biopotential Measurement, PBS0032A"
U9: "Mixed-Signal Microcontrollers, RGC0064B"
Y1: "Crystal, 32.768kHz, 12.5pF, SMD"
ZZ1: library part AssemblyNoteLabel
ZZ2 ZZ3 ZZ4: library part AssemblyNote

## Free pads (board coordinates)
  round 0 hole 3.762 unplated: 0(87.706,88.062)

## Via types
v1: diameter 0.864, hole 0.406, Top Layer to Bottom Layer, 104 vias
v2: diameter 0.5, hole 0.2, Top Layer to Bottom Layer, 13 vias

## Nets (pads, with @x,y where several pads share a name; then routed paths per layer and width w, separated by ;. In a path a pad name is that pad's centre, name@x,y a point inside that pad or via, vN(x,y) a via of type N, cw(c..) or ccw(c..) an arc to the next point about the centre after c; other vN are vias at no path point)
3V: C3.1 C4.1 C35.1 R4.2 R5.2 R15.2 U1.1 U1.3 U5.4 | length 53.6
  Top Layer w0.254: U1.3@92.945,102.55 U1.3@93.022,102.628 ; 94.183,100.178 94.285,100.178 ; C3.1@94.466,102.55 C3.1@94.544,102.628 ; 96.46,106.02 96.46,106.061
  Top Layer w0.54: R15.2@92.812,104.496 96.46,104.496 ; U1.1@92.945,100.65 93.711,100.65 94.183,100.178 ; U1.3@92.945,102.55 C3.1@94.466,102.55 ; 94.285,100.178 97.638,100.178 98.146,100.686 98.146,101.702 95.698,104.15 96.46,104.496 ; C3.1@94.544,102.628 C4.1@95.814,102.628 95.814,104.034 ; U5.4@95.443,109.662 95.443,110.632 95.809,110.998 97.282,110.998 97.79,110.49 ; C35.1@95.647,105.41 96.46,105.41 ; 96.46,106.02 96.46,105.41 ; 96.46,106.061 97.079,106.68 97.079,107.696 97.384,108.001 97.384,110.084 97.79,110.49 ; v1(100.432,113.132) 97.79,110.49 ; v1(102.972,115.672) 105.766,115.672 112.557,122.463 R5.2@112.557,124.816 ; R4.2@112.538,126.365 112.557,126.346 R5.2@112.557,124.861 ; 96.46,104.496 96.46,105.41
  Bottom Layer w0.54: v1(100.432,113.132) v1(102.972,115.672)
ADS1292_DRDY: 9.1 U8.22 U9.16 | length 19.6
  Top Layer w0.254: U8.22@89.244,138.704 89.244,137.039 89.51,136.773 v1(89.51,136.754) ; U9.16@94.418,128.312 v1(95.8,128.312) 96.114,127.998 9.1@96.114,127.356
  Bottom Layer w0.254: v1(89.51,136.754) 89.51,134.602 93.454,130.658 ; 93.454,130.658 v1(95.8,128.312) 95.8,129.448 94.59,130.658 93.454,130.658
ADS1292_ELA: C52.1 J3.2 R30.1 TP4.1 | length 93.4
  Top Layer w1: R30.1@83.562,151.409 83.562,154.733 ; J3.2@87.324,160.454 87.325,157.302 ; C52.1@93.32,152.086 93.32,153.518 92.05,154.788 83.562,154.733 ; TP4.1@145.059,143.358 145.059,153.822 141.58,157.302 88.494,157.302 84.836,157.302 83.562,156.028 83.562,154.733
ADS1292_ERA: C48.1 J3.1 R23.1 TP3.1 | length 92.4
  Top Layer w0.54: R23.1@84.836,151.437 v1@84.836,153.67
  Top Layer w1: TP3.1@28.626,143.358 28.626,153.822 31.217,156.413 78.867,156.413 82.908,160.454 J3.1@84.554,160.454 ; v1(94.539,155.143) 94.59,155.092 C48.1@94.59,152.086
  Bottom Layer w0.54: v1@84.836,153.67 85.649,154.534
  Bottom Layer w1: J3.1@84.554,160.454 84.554,156.873 84.836,156.591 84.836,153.67 v1(84.836,153.314) ; 85.039,155.143 v1(94.539,155.143)
ADS1292_GPIO1: 6.1 U8.26 U9.14 | length 24.5
  Top Layer w0.254: U8.26@91.643,140.603 93.026,140.603 94.541,139.089 94.541,137.976 96.525,135.992 ; U9.14@94.418,127.312 95.142,127.312 96.864,125.59 v1@96.864,125.336 ; 6.1@95.098,131.674 95.968,131.674 v1(96.374,132.08) 96.53,132.236 96.53,135.992
  Bottom Layer w0.254: v1(96.374,132.08) 98.4,130.055 98.4,126.848 v1(96.876,125.324)
ADS1292_GPIO2: 7.1 U8.25 U9.25 | length 20.5
  Top Layer w0.254: U9.25@89.768,128.962 89.768,129.729 ; 89.767,129.73 89.767,131.626 90.983,132.842 95.555,132.842 96.114,133.401 96.114,135.839 94.087,137.866 94.087,138.8 92.784,140.103 U8.25@91.643,140.103 ; 89.767,131.166 7.1@91.288,131.166
ADS1292_IN1N: C46.1 R24.1 R25.2 U8.3 | length 12.8
  Top Layer w0.254: R24.1@89.094,152.202 89.764,152.202 ; U8.3@89.244,145.003 89.244,148.184 89.51,148.45 v1(89.51,148.946) ; 89.319,147.753 90.003,147.753 C46.1@90.688,148.438 ; v1(89.764,153.264) 89.764,152.202 ; R25.2@90.688,152.202 89.764,152.202
  Bottom Layer w0.254: v1(89.51,148.946) 89.51,150.932 89.764,151.186 v1(89.764,153.264)
ADS1292_IN1P: C54.1 R28.1 R29.2 U8.4 | length 9.1
  Top Layer w0.254: U8.4@88.744,145.003 88.744,149.246 89.205,149.708 C54.1@90.688,149.708 ; R28.1@89.094,150.932 89.891,150.932 ; 89.891,149.835 89.891,150.932 ; R29.2@90.688,150.932 89.891,150.932
ADS1292_IN2N: C44.1 R23.2 U8.5 | length 8.7
  Top Layer w0.254: C44.1@86.36,150.291 84.89,150.291 R23.2@84.836,150.237 84.836,149.447 85.192,149.092 86.076,149.092 86.36,148.807 88.244,146.924 U8.5@88.244,145.003
ADS1292_IN2P: C57.1 R30.2 U8.6 | length 9.5
  Top Layer w0.254: C57.1@82.038,150.263 83.508,150.263 R30.2@83.562,150.209 ; R30.2@83.508,150.209 83.508,149.359 84.23,148.638 85.888,148.638 87.744,146.782 U8.6@87.744,145.003
ADS1292_MAIN_CLKSEL: 14.1 U8.14 U9.32 | length 17.1
  Top Layer w0.254: U8.14@85.344,141.103 83.934,141.103 83.268,140.437 83.268,130.658 83.776,130.15 85.954,130.15 ; 14.1@85.954,130.912 85.954,130.15 ; U9.32@86.267,128.962 86.267,129.837 85.954,130.15
ADS1292_RESET: 8.1 U8.15 U9.31 | length 16.9
  Top Layer w0.254: 8.1@85.192,132.944 85.192,131.597 ; U8.15@85.344,140.603 85.324,140.583 84.23,140.583 83.722,140.075 83.722,132.128 84.252,131.597 85.192,131.597 ; U9.31@86.767,128.962 86.767,131.368 86.538,131.597 85.192,131.597
ADS1292_RESP_MODP/IN3N: R26.2 U8.32 | length 2.4
  Top Layer w0.254: U8.32@91.643,143.603 93.311,143.603 93.32,143.612 R26.2@93.32,144.328
ADS1292_RESP_MODP/IN3P: R27.2 TP6.1 U8.31 | length 13.4
  Top Layer w0.254: U8.31@91.643,143.103 93.365,143.103 R27.2@94.59,144.328 97.592,144.328 98.4,145.136 TP6.1@98.4,150.901
ADS1292_RLD: J3.4 R22.2 TP5.1 | length 3.2
  Top Layer w0.254: R22.2@103.064,147.168 104.75,147.168 v1(105.258,146.66)
  Bottom Layer w0.254: v1(105.258,146.66) 105.791,146.126
ADS1292_SPI_CS: 10.1 U8.18 U9.29 | length 14.1
  Top Layer w0.254: 85.284,135.23 10.1@86.462,135.23 ; 87.198,137.328 86.411,136.541 85.792,136.541 85.192,135.941 85.192,134.722 85.446,134.468 87.07,134.468 87.767,133.771 U9.29@87.767,128.962 ; 87.244,137.374 U8.18@87.244,138.704
ADS1292_SPI_DIN: 12.1 U8.19 U9.26 | length 17.3
  Top Layer w0.254: 12.1@81.89,135.23 81.89,135.992 82.144,136.246 v1(82.144,136.5) ; v1@87.744,136.766 U8.19@87.744,138.704 ; U9.26@89.267,128.962 89.267,132.143 v1(89.713,132.588)
  Bottom Layer w0.254: v1(82.144,136.5) v1(87.478,136.5) 87.478,134.823 v1(89.713,132.588)
ADS1292_SPI_DOUT: 11.1 U8.21 U9.27 | length 29.7
  Top Layer w0.254: U9.27@88.767,128.962 88.767,134.074 88.744,134.098 U8.21@88.744,138.704 88.744,140.052 v1(89.51,140.818) ; v1(99.924,147.93) 99.924,149.2 11.1@101.956,151.232
  Bottom Layer w0.254: v1(89.51,140.818) 93.574,144.882 96.876,144.882 v1(99.924,147.93)
ADS1292_SPI_SCLK: 13.1 U8.20 U9.28 | length 21.9
  Top Layer w0.254: 13.1@81.839,147.32 82.601,146.558 84.125,146.558 v1(84.633,146.05) ; v1(87.732,140.31) 88.24,139.802 88.24,133.96 88.267,133.932 U9.28@88.267,128.962
  Bottom Layer w0.254: v1(84.633,146.05) 84.633,143.408 v1(87.732,140.31)
ADS1292_START: 15.1 U8.16 U9.30 | length 15.2
  Top Layer w0.254: 84.176,137.77 15.1@84.938,137.77 ; U8.16@85.344,140.103 84.458,140.103 84.176,139.821 84.176,138.204 84.176,134.722 84.938,133.96 86.716,133.96 87.267,133.408 U9.30@87.267,128.962
ADS1292_VCAP1: C55.1 U8.11 | length 4.6
  Top Layer w0.254: C55.1@80.765,142.603 U8.11@85.344,142.603
ADS1292_VCAP2: C56.1 U8.27 | length 6.8
  Top Layer w0.254: U8.27@91.643,141.103 93.442,141.103 94.995,139.55 94.995,138.022 95.501,137.516 C56.1@96.022,137.516
ADS1292_VREFP: C50.1 C51.1 U8.9 | length 5.9
  Top Layer w0.254: C51.1@81.626,145.58 C51.1@81.331,145.58 81.439,145.472 C50.1@82.855,145.472 83.687,145.472 83.871,145.288 83.871,144.018 84.286,143.603 U8.9@85.344,143.603
ADS_AVCC: C22.1 C23.1 C24.1 C39.1 C40.1 L6.2 R8.2 R24.2 R28.2 U2.5 U8.12 | length 21.4
  Top Layer w0.254: U2.5@76.094,143.8 77.048,143.8 77.267,144.018 v1(77.267,144.78) ; v1(76.505,145.542) 76.554,145.493 77.726,145.493 78.334,146.101 R8.2@78.334,147.33 ; v1(78.283,136.906) 78.646,137.27 79.5,137.27 C23.1@79.558,137.212 ; v1(78.876,141.106) C39.1@80.828,141.106 ; L6.2@79.604,135.522 79.604,137.166 C23.1@79.558,137.212 ; v1(80.62,148.184) C24.1@80.62,150.378 ; C22.1@80.828,137.212 C23.1@79.558,137.212 ; C39.1@81.128,141.164 C40.1@82.398,141.164 83.337,142.103 U8.12@85.344,142.103 ; v1(87.894,149.362) R28.2@87.894,150.932 R24.2@87.894,152.202
ADS_AVSS: C22.2 C23.2 C24.2 C39.2 C40.2 C44.2 C50.2 C51.2 C55.2 C56.2 C57.2 J3.10 J3.11 R3.2 R9.1 R12.1 R25.1 R29.1 U2.2 U3.2 U8.10 U8.13 | length 43.8
  Top Layer w0.254: v1(68.003,123.489) R3.2@69.818,123.489 ; v1(72.608,142.85) U2.2@73.694,142.85 ; R12.1@75.748,148.117 74.778,149.088 74.778,151.74 75.474,152.436 78.726,152.436 80.554,152.436 ; v1@77.826,143.612 v1(78.08,143.612) 78.08,143.205 78.689,142.596 C55.2@79.558,142.596 ; v1(79.807,146.304) 79.807,144.272 80.099,143.98 C51.2@81.331,143.98 81.623,144.272 C50.2@82.855,144.272 82.855,143.51 83.261,143.104 83.87,143.104 U8.10@85.344,143.103 ; C24.2@80.62,151.578 v1(80.62,153.518) ; C22.2@80.828,138.412 79.558,138.412 79.558,139.906 80.828,139.906 81.994,139.906 C40.2@82.225,140.137 ; C57.2@82.038,151.863 v1(82.038,153.496) ; C40.2@82.398,139.964 82.398,140.068 83.691,141.362 ; 83.691,141.373 83.922,141.603 U8.13@85.344,141.603 ; C44.2@86.36,151.891 v1(86.36,153.416) ; R29.1@91.888,150.932 R25.1@91.888,152.202 v1(91.888,153.426) ; C56.2@97.222,137.516 97.222,136.916 v1(97.638,136.5)
  Top Layer w0.54: v1(103.988,135.484) R9.1@103.988,137.17
  other v1: 79.858,139.906
ADS_DVCC: C15.1 C19.1 C20.1 C21.1 C41.1 C42.1 L5.2 L6.1 U8.23 | length 24.7
  Top Layer w0.254: L6.1@79.604,133.972 79.858,133.972 v1(79.858,132.436) ; 89.51,135.484 89.51,134.376 89.764,134.122 C42.1@90.526,134.122 C41.1@91.796,134.122 C19.1@93.066,134.122 C20.1@94.336,134.122 ; 89.526,135.5 90.272,136.246 90.272,137.008 89.744,137.536 U8.23@89.744,138.704 ; C20.1@94.364,134.15 C20.1@94.336,134.122 ; v1(95.301,133.858) 95.301,133.896 95.075,134.122 C20.1@94.336,134.122 ; v1(97.638,132.944) C21.1@97.638,134.122 98.308,133.452 L5.2@99.632,133.452 99.632,134.176 100.686,135.23 100.686,139.294 99.924,140.056 C15.1@99.924,141.296
ANTENNA: D1.2 D2.2 R13.2 R14.2 | length 600.2
  Top Layer w0.4: v1(77.064,95.86) 77.826,96.622 98.654,96.622 98.654,73 76.302,73 76.302,97.13 99.162,97.13 99.162,72.492 75.794,72.492 75.794,97.638 99.67,97.638 99.67,71.984 75.235,71.984 75.235,98.044 76.048,98.857 76.048,103.631 76.603,104.055 77.694,104.055 ; v1(77.064,100.178) 77.064,101.702 77.673,102.311 84.43,102.311 84.76,102.641 D2.2@84.76,103.239 ; D1.2@77.694,106.379 77.694,104.055 ; R13.2@79.472,104.055 77.694,104.055 ; 80.996,102.311 R14.2@80.996,104.055
  Bottom Layer w0.4: 75.235,97.079 75.235,71.984 99.67,71.984 99.67,97.638 77.064,97.638 v1(77.064,100.178) ; 75.286,97.13 99.162,97.13 99.162,72.492 75.794,72.492 75.794,96.622 98.654,96.622 98.654,73 76.302,73 76.302,95.098 v1(77.064,95.86)
BMA_AVCC: C16.1 C37.1 L4.1 U6.7 | length 5.4
  Top Layer w0.254: C16.1@74.016,128.647 C37.1@75.286,128.647 ; U6.7@75.019,127.111 75.019,128.38 C37.1@75.286,128.647 ; L4.1@76.772,129.896 76.772,129.045 76.532,128.805 75.444,128.805 C37.1@75.286,128.647
BMA_DVCC: C17.1 C36.1 L3.2 L4.2 U6.1 U6.3 U6.11 | length 28.6
  Top Layer w0.254: U6.11@75.544,125.586 75.544,124.794 75.26,124.511 73.914,124.511 72.644,125.781 72.644,129.616 74.143,131.115 78.003,131.115 78.372,130.747 L4.2@78.372,129.896 78.372,129.096 79.35,128.118 L3.2@80.328,128.118 80.366,128.08 C17.1@80.366,126.224 C36.1@79.096,126.224 78.709,126.611 U6.3@76.569,126.611 ; U6.1@76.569,125.611 76.569,125.158 77.013,124.714 77.876,124.714 78.359,125.197 78.359,126.585
BMA_INT1: U6.5 U9.38 | length 11
  Top Layer w0.254: U6.5@76.044,127.136 76.044,127.657 76.179,127.792 v1(76.654,127.792) ; v1(82.144,126.848) 83.16,125.832 ; 83.18,125.812 U9.38@85.618,125.812
  Bottom Layer w0.254: v1(76.654,127.792) 77.623,127.792 78.641,126.774 79.187,126.774 79.261,126.848 v1(82.144,126.848)
BMA_INT2: U6.6 U9.33 | length 12.2
  Top Layer w0.254: U6.6@75.544,127.136 75.544,127.88 76.115,128.451 77.191,128.451 77.517,128.778 v1(77.597,128.778) ; v1(83.871,129.286) 83.871,128.676 84.236,128.312 U9.33@85.618,128.312
  Bottom Layer w0.254: v1(77.597,128.778) 83.363,128.778 v1(83.871,129.286)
